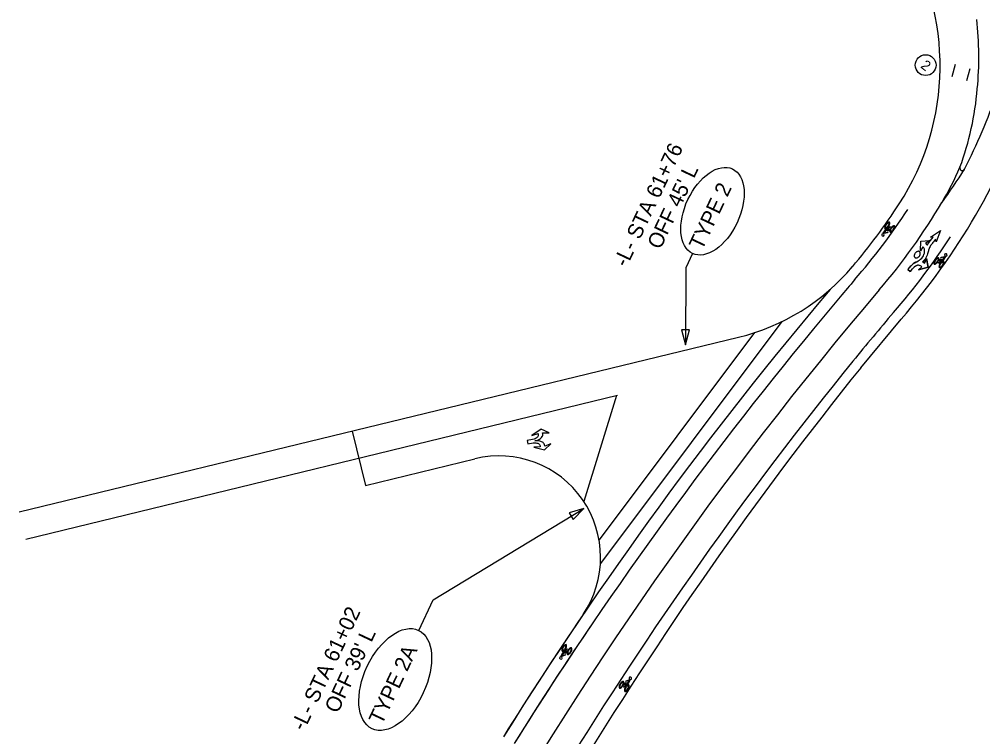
# Model space of a CAD drawing. Extents: x 553958 to 562499, y 493978 to 516388.
# Drawn here: x 561385.7 to 561765, y 497450.3 to 497732.6 of the extents above; entities that cross this region are included whole.
import ezdxf

# ---------------------------------------------------------------- set-up
doc = ezdxf.new("R2010")
doc.units = 0
for name, color, linetype in [('Exist Horizontal Alignment', 7, 'Continuous'), ('Prop DSN Text', 7, 'Continuous'), ('Prop EOT', 7, 'Continuous'), ('Prop Horizontal Alignment Tick Small', 7, 'Continuous'), ('Prop Plan Preparation Excavation Hatching', 7, 'Continuous'), ('Prop SS Fill Line', 7, 'Continuous'), ('Scratch_Level_4', 7, 'Continuous'), ('Sheet North Arrow CELL', 7, 'Continuous'), ('Sheet Plan CELL', 7, 'Continuous'), ('Sheet Plot Border Inside CELL', 7, 'Continuous'), ('Sheet Plot Border Outside CELL', 7, 'Continuous')]:
    doc.layers.add(name, color=color, linetype=linetype)

msp = doc.modelspace()

# ---------------------------------------------------------------- linework, layer by layer
at = {"layer": 'Exist Horizontal Alignment'}
for centre, radius, start, end in [((561536.66, 497815.01), 262.5, 323.9325, 327.4099), ((561756.94, 497674.07), 1, 159.6609, 333.2802)]:
    msp.add_arc(centre, radius, start, end, dxfattribs=at)
at = {"layer": 'Prop DSN Text'}
msp.add_circle((561742.49, 497714.61), 4.09, dxfattribs=at)
for centre, major_axis, ratio in [((561658.59, 497657.1), (7.87, 16.64), 0.581481), ((561533.72, 497472.81), (9.15, 19.35), 0.570089)]:
    msp.add_ellipse(centre, major_axis=major_axis, ratio=ratio, dxfattribs=at)
at = {"layer": 'Prop EOT'}
msp.add_lwpolyline([(561744.35, 497646.85), (561748.3, 497649.56), (561746.6, 497645.08), (561746.4, 497646.1), (561745.6, 497645.08), (561745.33, 497644.74), (561745.07, 497644.39), (561744.92, 497644.19), (561744.67, 497643.86), (561744.46, 497643.56), (561744.27, 497643.26), (561744.05, 497642.88), (561743.91, 497642.57), (561743.82, 497642.32), (561743.75, 497642.13), (561743.63, 497641.77), (561743.56, 497641.49), (561743.46, 497641.07), (561743.28, 497640.35), (561743.1, 497639.84), (561742.85, 497639.26), (561742.61, 497638.8), (561742.25, 497638.24), (561741.89, 497637.78), (561741.61, 497637.48), (561741.26, 497637.14), (561741.52, 497637.01), (561741.84, 497636.83), (561742.1, 497636.67), (561742.83, 497638.45), (561743.44, 497635.07), (561739.69, 497634.01), (561741.01, 497635.26), (561740.67, 497635.48), (561740.48, 497635.58), (561740.31, 497635.66), (561740.14, 497635.74), (561739.98, 497635.79), (561739.71, 497635.84), (561739.57, 497635.84), (561739.29, 497635.81), (561739.15, 497635.78), (561738.97, 497635.72), (561738.76, 497635.62), (561738.55, 497635.5), (561738.41, 497635.4), (561738.11, 497635.18), (561737.86, 497634.97), (561737.6, 497634.75), (561737.33, 497634.49), (561737.12, 497634.27), (561736.86, 497633.97), (561736.64, 497633.7), (561736.45, 497633.44), (561735.49, 497634.2), (561735.72, 497634.49), (561736.22, 497635.07), (561736.74, 497635.63), (561737.31, 497636.17), (561737.74, 497636.51), (561738.24, 497636.85), (561738.64, 497637.06), (561739.01, 497637.24), (561739.56, 497637.53), (561740.08, 497637.87), (561740.53, 497638.21), (561740.95, 497638.61), (561741.34, 497639.12), (561741.62, 497639.58), (561741.81, 497640.02), (561741.97, 497640.44), (561741.98, 497640.6), (561742.07, 497641.24), (561742.08, 497641.64), (561742, 497642.11), (561741.88, 497642.4), (561741.73, 497642.64), (561741.37, 497643.07), (561740.46, 497641.48), (561740.6, 497645.37), (561744.04, 497645.58), (561742.48, 497644.45), (561742.71, 497644.24), (561742.88, 497644.06), (561743.04, 497643.83), (561743.11, 497643.72), (561743.39, 497644.17), (561743.72, 497644.65), (561744.02, 497645.06), (561744.42, 497645.56), (561745.46, 497646.9)], close=True, dxfattribs=at)
for points in [[(561741.01, 497635.26), (561739.69, 497634.01), (561743.44, 497635.07), (561742.83, 497638.45), (561742.1, 497636.67)], [(561735.49, 497634.2), (561736.45, 497633.44)]]:
    msp.add_lwpolyline(points, dxfattribs=at)
for centre, radius, start, end in [((561739.39, 497639.53), 1.4, 164.5709, 187.3003), ((561738.78, 497639.45), 0.777, 187.3003, 207.5013), ((561739.98, 497639.37), 2.01, 156.586, 164.5709), ((561738.75, 497639.43), 0.742, 207.5013, 230.6149), ((561740.07, 497639.33), 2.1, 143.8868, 156.586), ((561738.66, 497639.33), 0.613, 230.6149, 231.8483), ((561738.66, 497639.33), 0.613, 231.8483, 233.0817), ((561738.74, 497639.44), 0.742, 233.0817, 256.1953), ((561739.97, 497639.4), 1.98, 141.8483, 143.8868), ((561739.97, 497639.4), 1.98, 139.8097, 141.8483), ((561740.06, 497639.32), 2.1, 127.1106, 139.8097), ((561738.75, 497639.47), 0.777, 256.1953, 276.3962), ((561740.01, 497639.4), 2.01, 119.1257, 127.1106), ((561738.68, 497640.09), 1.4, 276.3962, 299.1257), ((561739.71, 497639.93), 1.4, 96.3962, 119.1257), ((561738.38, 497640.62), 2.01, 299.1257, 307.1106), ((561739.64, 497640.55), 0.777, 76.1953, 96.3962), ((561738.33, 497640.7), 2.1, 307.1106, 319.8097), ((561739.65, 497640.58), 0.742, 53.0817, 76.1953), ((561738.42, 497640.62), 1.98, 319.8097, 321.8483), ((561738.42, 497640.62), 1.98, 321.8483, 323.8868), ((561738.32, 497640.69), 2.1, 323.8868, 336.586), ((561739.73, 497640.68), 0.613, 51.8483, 53.0817), ((561739.73, 497640.68), 0.613, 50.6149, 51.8483), ((561739.64, 497640.59), 0.742, 27.5013, 50.6149), ((561738.41, 497640.65), 2.01, 336.586, 344.5709), ((561739.61, 497640.57), 0.777, 7.3003, 27.5013), ((561739, 497640.49), 1.4, 344.5709, 7.3003), ((561753.18, 497619.96), 22.71, 136.3295, 141.1886), ((561743.17, 497628.69), 8.23, 124.1634, 144.7581), ((561741.99, 497630.69), 7.21, 118.5923, 136.5912), ((561733.39, 497648.83), 12.88, 293.5578, 295.8573), ((561739.71, 497633.78), 2.07, 105.7646, 123.9716), ((561739.64, 497633.97), 1.88, 89.0984, 105.2483), ((561739.48, 497633.92), 1.93, 61.3323, 84.4244), ((561738.21, 497631.15), 4.97, 55.7257, 63.7666), ((561738.89, 497631.93), 5.72, 55.8912, 65.5959), ((562861.22, 496646.67), 1515.52, 139.7289, 147.9767), ((562865.58, 496652.78), 1510, 139.99984, 140.62132), ((562861.22, 496646.67), 1510.52, 140.33726, 147.9767)]:
    msp.add_arc(centre, radius, start, end, dxfattribs=at)
at = {"layer": 'Prop Horizontal Alignment Tick Small'}
for p, q in [((561725.83, 497648.43), (561726.71, 497649.84)), ((561726.86, 497649.5), (561726.29, 497648.57)), ((561726.71, 497649.84), (561728.44, 497651.07)), ((561726.82, 497651.91), (561727.02, 497651.77)), ((561726.82, 497651.91), (561727.02, 497651.77)), ((561727.85, 497649.28), (561726.86, 497649.5)), ((561728.58, 497650.87), (561726.95, 497649.72)), ((561726.95, 497649.72), (561727.71, 497649.55)), ((561727.68, 497651.3), (561727.88, 497651.16)), ((561727.68, 497651.3), (561727.88, 497651.16)), ((561727.71, 497649.55), (561727.97, 497650.15)), ((561728.19, 497650.06), (561727.85, 497649.28)), ((561727.97, 497650.15), (561728.19, 497650.06)), ((561728.44, 497651.07), (561728.6, 497650.89)), ((561728.82, 497650.5), (561729.01, 497650.36)), ((561728.82, 497650.5), (561729.01, 497650.36)), ((561729.68, 497649.88), (561729.88, 497649.74)), ((561729.68, 497649.88), (561729.88, 497649.74)), ((561725.42, 497648.07), (561725.29, 497648.16)), ((561725.42, 497648.07), (561725.29, 497648.16)), ((561726.14, 497648.32), (561725.83, 497648.43)), ((561726.21, 497647.51), (561726.09, 497647.6)), ((561726.21, 497647.51), (561726.09, 497647.6)), ((561727.45, 497648.63), (561726.14, 497648.32)), ((561726.29, 497648.57), (561727.63, 497648.88)), ((561727.63, 497648.88), (561727.45, 497648.63)), ((561746.42, 497637.77), (561746.22, 497637.91)), ((561746.42, 497637.77), (561746.22, 497637.91)), ((561747.52, 497636.78), (561749.15, 497637.93)), ((561749.39, 497637.81), (561747.66, 497636.58)), ((561747.91, 497637.6), (561748.25, 497638.37)), ((561748.39, 497638.1), (561748.13, 497637.5)), ((561748.25, 497638.37), (561749.24, 497638.15)), ((561749.15, 497637.93), (561748.39, 497638.1)), ((561749.81, 497639.08), (561748.47, 497638.77)), ((561748.47, 497638.77), (561748.65, 497639.02)), ((561748.65, 497639.02), (561749.96, 497639.33)), ((561749.24, 497638.15), (561749.81, 497639.08)), ((561750.27, 497639.23), (561749.39, 497637.81)), ((561749.89, 497640.14), (561750.01, 497640.05)), ((561749.89, 497640.14), (561750.01, 497640.05)), ((561749.96, 497639.33), (561750.27, 497639.23)), ((561750.68, 497639.58), (561750.81, 497639.49)), ((561750.68, 497639.58), (561750.81, 497639.49)), ((561747.28, 497637.16), (561747.09, 497637.3)), ((561747.28, 497637.16), (561747.09, 497637.3)), ((561747.66, 497636.58), (561747.5, 497636.76)), ((561748.13, 497637.5), (561747.91, 497637.6)), ((561748.42, 497636.36), (561748.22, 497636.5)), ((561748.42, 497636.36), (561748.22, 497636.5)), ((561749.28, 497635.74), (561749.08, 497635.89)), ((561749.28, 497635.74), (561749.08, 497635.89)), ((561598.99, 497481.99), (561599.74, 497483.48)), ((561600.59, 497482.34), (561599.31, 497481.91)), ((561599.92, 497483.15), (561599.43, 497482.18)), ((561599.43, 497482.18), (561600.74, 497482.61)), ((561599.65, 497485.55), (561599.86, 497485.42)), ((561599.65, 497485.55), (561599.86, 497485.42)), ((561599.74, 497483.48), (561601.34, 497484.86)), ((561600.92, 497483.03), (561599.92, 497483.15)), ((561601.5, 497484.68), (561599.99, 497483.38)), ((561599.99, 497483.38), (561600.76, 497483.29)), ((561600.57, 497485.02), (561600.78, 497484.9)), ((561600.57, 497485.02), (561600.78, 497484.9)), ((561600.74, 497482.61), (561600.59, 497482.34)), ((561600.76, 497483.29), (561600.96, 497483.9)), ((561601.18, 497483.83), (561600.92, 497483.03)), ((561600.96, 497483.9), (561601.18, 497483.83)), ((561601.34, 497484.86), (561601.52, 497484.7)), ((561601.77, 497484.33), (561601.98, 497484.21)), ((561601.77, 497484.33), (561601.98, 497484.21)), ((561602.69, 497483.8), (561602.9, 497483.68)), ((561602.69, 497483.8), (561602.9, 497483.68)), ((561598.61, 497481.6), (561598.48, 497481.67)), ((561598.61, 497481.6), (561598.48, 497481.67)), ((561599.31, 497481.91), (561598.99, 497481.99)), ((561599.46, 497481.11), (561599.32, 497481.19)), ((561599.46, 497481.11), (561599.32, 497481.19)), ((561622.43, 497470.91), (561622.22, 497471.03)), ((561622.43, 497470.91), (561622.22, 497471.03)), ((561623.59, 497469.99), (561625.14, 497471.25)), ((561625.38, 497471.15), (561623.74, 497469.81)), ((561623.93, 497470.84), (561624.21, 497471.63)), ((561624.15, 497470.76), (561623.93, 497470.84)), ((561624.37, 497471.37), (561624.15, 497470.76)), ((561624.21, 497471.63), (561625.21, 497471.48)), ((561625.14, 497471.25), (561624.37, 497471.37)), ((561625.72, 497472.44), (561624.4, 497472.05)), ((561624.4, 497472.05), (561624.56, 497472.31)), ((561624.56, 497472.31), (561625.85, 497472.7)), ((561625.21, 497471.48), (561625.72, 497472.44)), ((561626.17, 497472.62), (561625.38, 497471.15)), ((561625.73, 497473.51), (561625.86, 497473.43)), ((561625.73, 497473.51), (561625.86, 497473.43)), ((561625.85, 497472.7), (561626.17, 497472.62)), ((561626.56, 497473), (561626.69, 497472.92)), ((561626.56, 497473), (561626.69, 497472.92)), ((561623.33, 497470.36), (561623.12, 497470.48)), ((561623.33, 497470.36), (561623.12, 497470.48)), ((561623.74, 497469.81), (561623.57, 497469.98)), ((561624.51, 497469.63), (561624.3, 497469.76)), ((561624.51, 497469.63), (561624.3, 497469.76)), ((561625.42, 497469.08), (561625.21, 497469.21)), ((561625.42, 497469.08), (561625.21, 497469.21))]:
    msp.add_line(p, q, dxfattribs=at)
for centre, radius, start, end in [((561725.75, 497647.83), 0.563, 144.7423, 324.7423), ((561725.75, 497647.83), 0.563, 144.7423, 324.7423), ((561725.75, 497647.83), 0.41, 324.7423, 144.7423), ((561750.35, 497639.82), 0.563, 324.7423, 144.7423), ((561750.35, 497639.82), 0.563, 324.7423, 144.7423), ((561750.35, 497639.82), 0.41, 144.7423, 324.7423), ((561598.97, 497481.39), 0.563, 150.099, 330.099), ((561598.97, 497481.39), 0.563, 150.099, 330.099), ((561598.97, 497481.39), 0.41, 330.099, 150.099), ((561626.21, 497473.22), 0.563, 328.5834, 148.5834), ((561626.21, 497473.22), 0.563, 328.5834, 148.5834), ((561626.21, 497473.22), 0.41, 148.5834, 328.5834)]:
    msp.add_arc(centre, radius, start, end, dxfattribs=at)
for centre, major_axis, ratio, start_param, end_param in [((561727.35, 497651.53), (0.86, 1.22), 0.435841, 4.712389, 7.853982), ((561727.35, 497651.53), (0.86, 1.22), 0.435841, 1.570796, 4.712389), ((561727.35, 497651.53), (0.72, 1.02), 0.325967, 1.570796, 4.712389), ((561727.35, 497651.53), (0.72, 1.02), 0.325967, 4.712389, 7.853982), ((561729.35, 497650.12), (0.86, 1.22), 0.435841, 1.570796, 4.712389), ((561729.35, 497650.12), (0.72, 1.02), 0.325967, 1.570796, 4.712389), ((561729.35, 497650.12), (0.86, 1.22), 0.435841, 4.712389, 7.853982), ((561729.35, 497650.12), (0.72, 1.02), 0.325967, 4.712389, 7.853982), ((561746.75, 497637.53), (-0.86, -1.22), 0.435841, 4.712389, 7.853982), ((561746.75, 497637.53), (-0.72, -1.02), 0.325967, 4.712389, 7.853982), ((561746.75, 497637.53), (-0.86, -1.22), 0.435841, 1.570796, 4.712389), ((561746.75, 497637.53), (-0.72, -1.02), 0.325967, 1.570796, 4.712389), ((561748.75, 497636.12), (-0.86, -1.22), 0.435841, 4.712389, 7.853982), ((561748.75, 497636.12), (-0.72, -1.02), 0.325967, 4.712389, 7.853982), ((561748.75, 497636.12), (-0.86, -1.22), 0.435841, 1.570796, 4.712389), ((561748.75, 497636.12), (-0.72, -1.02), 0.325967, 1.570796, 4.712389), ((561600.21, 497485.22), (0.75, 1.3), 0.435841, 4.712389, 7.853982), ((561600.21, 497485.22), (0.62, 1.08), 0.325967, 4.712389, 7.853982), ((561600.21, 497485.22), (0.75, 1.3), 0.435841, 1.570796, 4.712389), ((561600.21, 497485.22), (0.62, 1.08), 0.325967, 1.570796, 4.712389), ((561602.33, 497484), (0.75, 1.3), 0.435841, 1.570796, 4.712389), ((561602.33, 497484), (0.62, 1.08), 0.325967, 1.570796, 4.712389), ((561602.33, 497484), (0.75, 1.3), 0.435841, 4.712389, 7.853982), ((561602.33, 497484), (0.62, 1.08), 0.325967, 4.712389, 7.853982), ((561622.77, 497470.7), (-0.78, -1.28), 0.435841, 4.712389, 7.853982), ((561622.77, 497470.7), (-0.65, -1.07), 0.325967, 4.712389, 7.853982), ((561622.77, 497470.7), (-0.78, -1.28), 0.435841, 1.570796, 4.712389), ((561622.77, 497470.7), (-0.65, -1.07), 0.325967, 1.570796, 4.712389), ((561624.86, 497469.42), (-0.78, -1.28), 0.435841, 1.570796, 4.712389), ((561624.86, 497469.42), (-0.78, -1.28), 0.435841, 4.712389, 7.853982), ((561624.86, 497469.42), (-0.65, -1.07), 0.325967, 4.712389, 7.853982), ((561624.86, 497469.42), (-0.65, -1.07), 0.325967, 1.570796, 4.712389)]:
    msp.add_ellipse(centre, major_axis=major_axis, ratio=ratio, start_param=start_param, end_param=end_param, dxfattribs=at)
at = {"layer": 'Prop Plan Preparation Excavation Hatching'}
for points in [[(561588.61, 497566.71), (561589.13, 497566.81), (561589.53, 497566.92), (561589.95, 497567.07), (561590.3, 497567.25), (561590.56, 497567.41), (561590.9, 497567.66), (561591.12, 497567.87), (561591.35, 497568.11), (561591.57, 497568.41), (561591.68, 497568.64), (561591.77, 497568.95), (561591.8, 497569.35), (561591.71, 497569.89), (561594.28, 497569.84), (561591.1, 497571.27), (561587.5, 497568.87), (561589.95, 497569.6), (561590.02, 497569.16), (561590.04, 497568.91), (561589.97, 497568.66), (561589.86, 497568.46), (561589.67, 497568.19), (561589.48, 497568), (561589.14, 497567.76), (561588.74, 497567.57), (561588.34, 497567.41), (561587.76, 497567.26), (561585.63, 497566.91), (561585.74, 497566.25)], [(561588.61, 497566.71), (561589.13, 497566.81), (561589.53, 497566.92), (561589.95, 497567.07), (561590.3, 497567.25), (561590.56, 497567.41), (561590.9, 497567.66), (561591.12, 497567.87), (561591.35, 497568.11), (561591.57, 497568.41), (561591.68, 497568.64), (561591.77, 497568.95), (561591.8, 497569.35), (561591.71, 497569.89), (561594.28, 497569.84), (561591.1, 497571.27), (561587.5, 497568.87), (561589.95, 497569.6), (561590.02, 497569.16), (561590.04, 497568.91), (561589.97, 497568.66), (561589.86, 497568.46), (561589.67, 497568.19), (561589.48, 497568), (561589.14, 497567.76), (561588.74, 497567.57), (561588.34, 497567.41), (561587.76, 497567.26), (561585.63, 497566.91), (561585.74, 497566.25)], [(561585.74, 497566.25), (561585.85, 497565.58), (561587.98, 497565.93), (561588.57, 497565.97), (561589.01, 497565.94), (561589.45, 497565.88), (561589.84, 497565.76), (561590.08, 497565.64), (561590.34, 497565.44), (561590.51, 497565.29), (561590.65, 497565.07), (561590.72, 497564.83), (561590.79, 497564.38), (561588.24, 497564.31), (561592.41, 497563.16), (561594.97, 497565.51), (561592.55, 497564.67), (561592.46, 497565.2), (561592.31, 497565.58), (561592.13, 497565.84), (561591.95, 497566.03), (561591.65, 497566.25), (561591.35, 497566.4), (561591.08, 497566.53), (561590.68, 497566.66), (561590.39, 497566.73), (561590, 497566.79), (561589.55, 497566.8), (561589.14, 497566.78), (561588.61, 497566.71)], [(561585.74, 497566.25), (561585.85, 497565.58), (561587.98, 497565.93), (561588.57, 497565.97), (561589.01, 497565.94), (561589.45, 497565.88), (561589.84, 497565.76), (561590.08, 497565.64), (561590.34, 497565.44), (561590.51, 497565.29), (561590.65, 497565.07), (561590.72, 497564.83), (561590.79, 497564.38), (561588.24, 497564.31), (561592.41, 497563.16), (561594.97, 497565.51), (561592.55, 497564.67), (561592.46, 497565.2), (561592.31, 497565.58), (561592.13, 497565.84), (561591.95, 497566.03), (561591.65, 497566.25), (561591.35, 497566.4), (561591.08, 497566.53), (561590.68, 497566.66), (561590.39, 497566.73), (561590, 497566.79), (561589.55, 497566.8), (561589.14, 497566.78), (561588.61, 497566.71)]]:
    msp.add_lwpolyline(points, dxfattribs=at)
at = {"layer": 'Prop SS Fill Line'}
for p, q in [((561385.73, 497538.75), (561668.79, 497607.52)), ((561516.8, 497570.59), (561521.99, 497549.21)), ((561521.99, 497549.21), (561565.11, 497559.69))]:
    msp.add_line(p, q, dxfattribs=at)
for centre, radius, start, end in [((561574.55, 497520.82), 40, 325.8082, 103.6556), ((562861.22, 496646.67), 1515.52, 145.8082, 147.9767)]:
    msp.add_arc(centre, radius, start, end, dxfattribs=at)
at = {"layer": 'Scratch_Level_4'}
for p, q in [((561754.1, 497714.78), (561752.77, 497709.96)), ((561759.88, 497713.19), (561758.56, 497708.37)), ((561685.84, 497613.65), (561614.48, 497518.44)), ((561675.09, 497609.31), (561613.95, 497527.74))]:
    msp.add_line(p, q, dxfattribs=at)
at = {"layer": 'Sheet North Arrow CELL'}
msp.add_line((561620.82, 497584.55), (561607.95, 497542.83), dxfattribs=at)
at = {"layer": 'Sheet Plan CELL'}
for points in [[(561650.73, 497640.46), (561648.08, 497634.86), (561647.98, 497604.58)], [(561543.02, 497492.09), (561548.71, 497504.11), (561607.9, 497540.07)]]:
    msp.add_lwpolyline(points, dxfattribs=at)
for points in [[(561646.44, 497610.38), (561647.98, 497604.58), (561649.55, 497610.37)], [(561603.75, 497535.73), (561607.9, 497540.07), (561602.14, 497538.39)]]:
    msp.add_lwpolyline(points, close=True, dxfattribs=at)
at = {"layer": 'Sheet Plot Border Inside CELL'}
for p, q in [((561716.92, 497595.53), (561732.88, 497614.64)), ((561385.73, 497538.75), (561668.79, 497607.52)), ((561521.99, 497549.21), (561565.11, 497559.69))]:
    msp.add_line(p, q, dxfattribs=at)
for centre, radius, start, end in [((561648.17, 497714.39), 100, 327.065, 31.483), ((561635.43, 497717.95), 128.01, 354.3356, 6.5783), ((561648.17, 497714.39), 115, 339.6609, 355.4716), ((561531.14, 497787.73), 253.79, 333.2802, 340.6791), ((561534.03, 497788.33), 264, 318.8639, 340.6981), ((561534.03, 497788.33), 236, 319.5694, 327.065), ((561534.03, 497788.33), 240, 318.7731, 327.065), ((561534.03, 497788.33), 260, 318.8639, 327.065), ((561648.72, 497690.12), 85, 283.6556, 319.8234), ((562865.58, 496652.78), 1510, 139.66464, 139.99984), ((562865.58, 496652.78), 1490, 139.66464, 140.62132), ((562869.94, 496658.89), 1489.52, 140.90939, 148.54883), ((562873.93, 496665.26), 1484.61, 141.19962, 148.83906), ((561574.55, 497520.82), 40, 325.8082, 103.6556), ((562861.22, 496646.67), 1515.52, 145.8082, 147.9767), ((562861.22, 496646.67), 1510.52, 145.8082, 147.9767)]:
    msp.add_arc(centre, radius, start, end, dxfattribs=at)
at = {"layer": 'Sheet Plot Border Outside CELL'}
msp.add_line((561388.33, 497528.06), (561621.24, 497584.65), dxfattribs=at)
for centre, radius, start, end in [((561645.53, 497722.24), 120.38, 329.1248, 336.5921), ((561534.03, 497788.33), 250, 319.5426, 329.264), ((562865.58, 496652.78), 1500, 139.54257, 161.63616)]:
    msp.add_arc(centre, radius, start, end, dxfattribs=at)

# ---------------------------------------------------------------- texts
at = {"layer": 'Prop EOT'}
for s, height, rotation, p in [('2', 4, 321.6667, (561740.22, 497713.85)), ('-L- STA 61+76', 6, 64.7021, (561624.79, 497634.72)), ("OFF 45' L", 6, 64.7021, (561638.05, 497641.72)), ('TYPE 2', 6, 64.7021, (561654.51, 497641.45)), ('-L- STA 61+02', 6, 64.7021, (561497.83, 497452.22)), ("OFF 39' L", 6, 64.7021, (561511.07, 497459.15)), ('TYPE 2A', 6, 64.7021, (561528.47, 497454.68))]:
    msp.add_text(s, height=height, rotation=rotation, dxfattribs=at).set_placement(p)

doc.saveas('drawing.dxf')
